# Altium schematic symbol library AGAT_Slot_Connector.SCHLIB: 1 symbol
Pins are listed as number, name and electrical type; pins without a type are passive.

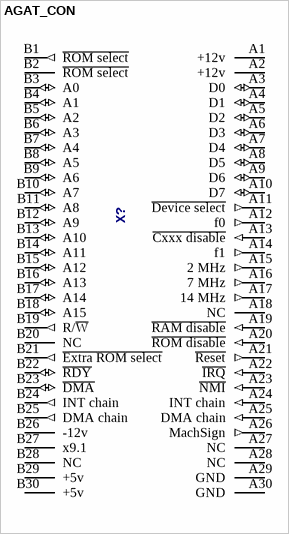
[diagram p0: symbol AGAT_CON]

## AGAT_CON
designator X?  (value not drawn)
footprint AGAT_CONP
pins: A1 +12v (power), A2 +12v (power), A3 D0 (io), A4 D1 (io), A5 D2 (io), A6 D3 (io), A7 D4 (io), A8 D5 (io), A9 D6 (io), A10 D7 (io), A11 ~{Device select} (out), A12 f0 (out), A13 ~{Cxxx disable} (in), A14 f1 (out), A15 2 MHz (out), A16 7 MHz (out), A17 14 MHz (out), A18 NC, A19 ~{RAM disable} (in), A20 ~{ROM disable} (in), A21 ~{Reset} (out), A22 ~{IRQ} (in), A23 ~{NMI} (in), A24 INT chain (in), A25 DMA chain (in), A26 MachSign (out), A27 NC, A28 NC, A29 GND (power), A30 GND (power), B1 ~{ROM select} (out), B2 ~{ROM select}, B3 A0 (io), B4 A1 (io), B5 A2 (io), B6 A3 (io), B7 A4 (io), B8 A5 (io), B9 A6 (io), B10 A7 (io), B11 A8 (io), B12 A9 (io), B13 A10 (io), B14 A11 (io), B15 A12 (io), B16 A13 (io), B17 A14 (io), B18 A15 (io), B19 R/~{W} (out), B20 NC, B21 ~{Extra ROM select} (out), B22 ~{RDY} (io), B23 ~{DMA} (io), B24 INT chain (out), B25 DMA chain (out), B26 -12v (power), B27 x9.1 (hiz), B28 NC, B29 +5v (power), B30 +5v (power)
